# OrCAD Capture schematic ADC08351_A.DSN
size B; title: SCHEMATIC; rev: A; note: ADC08351EVM
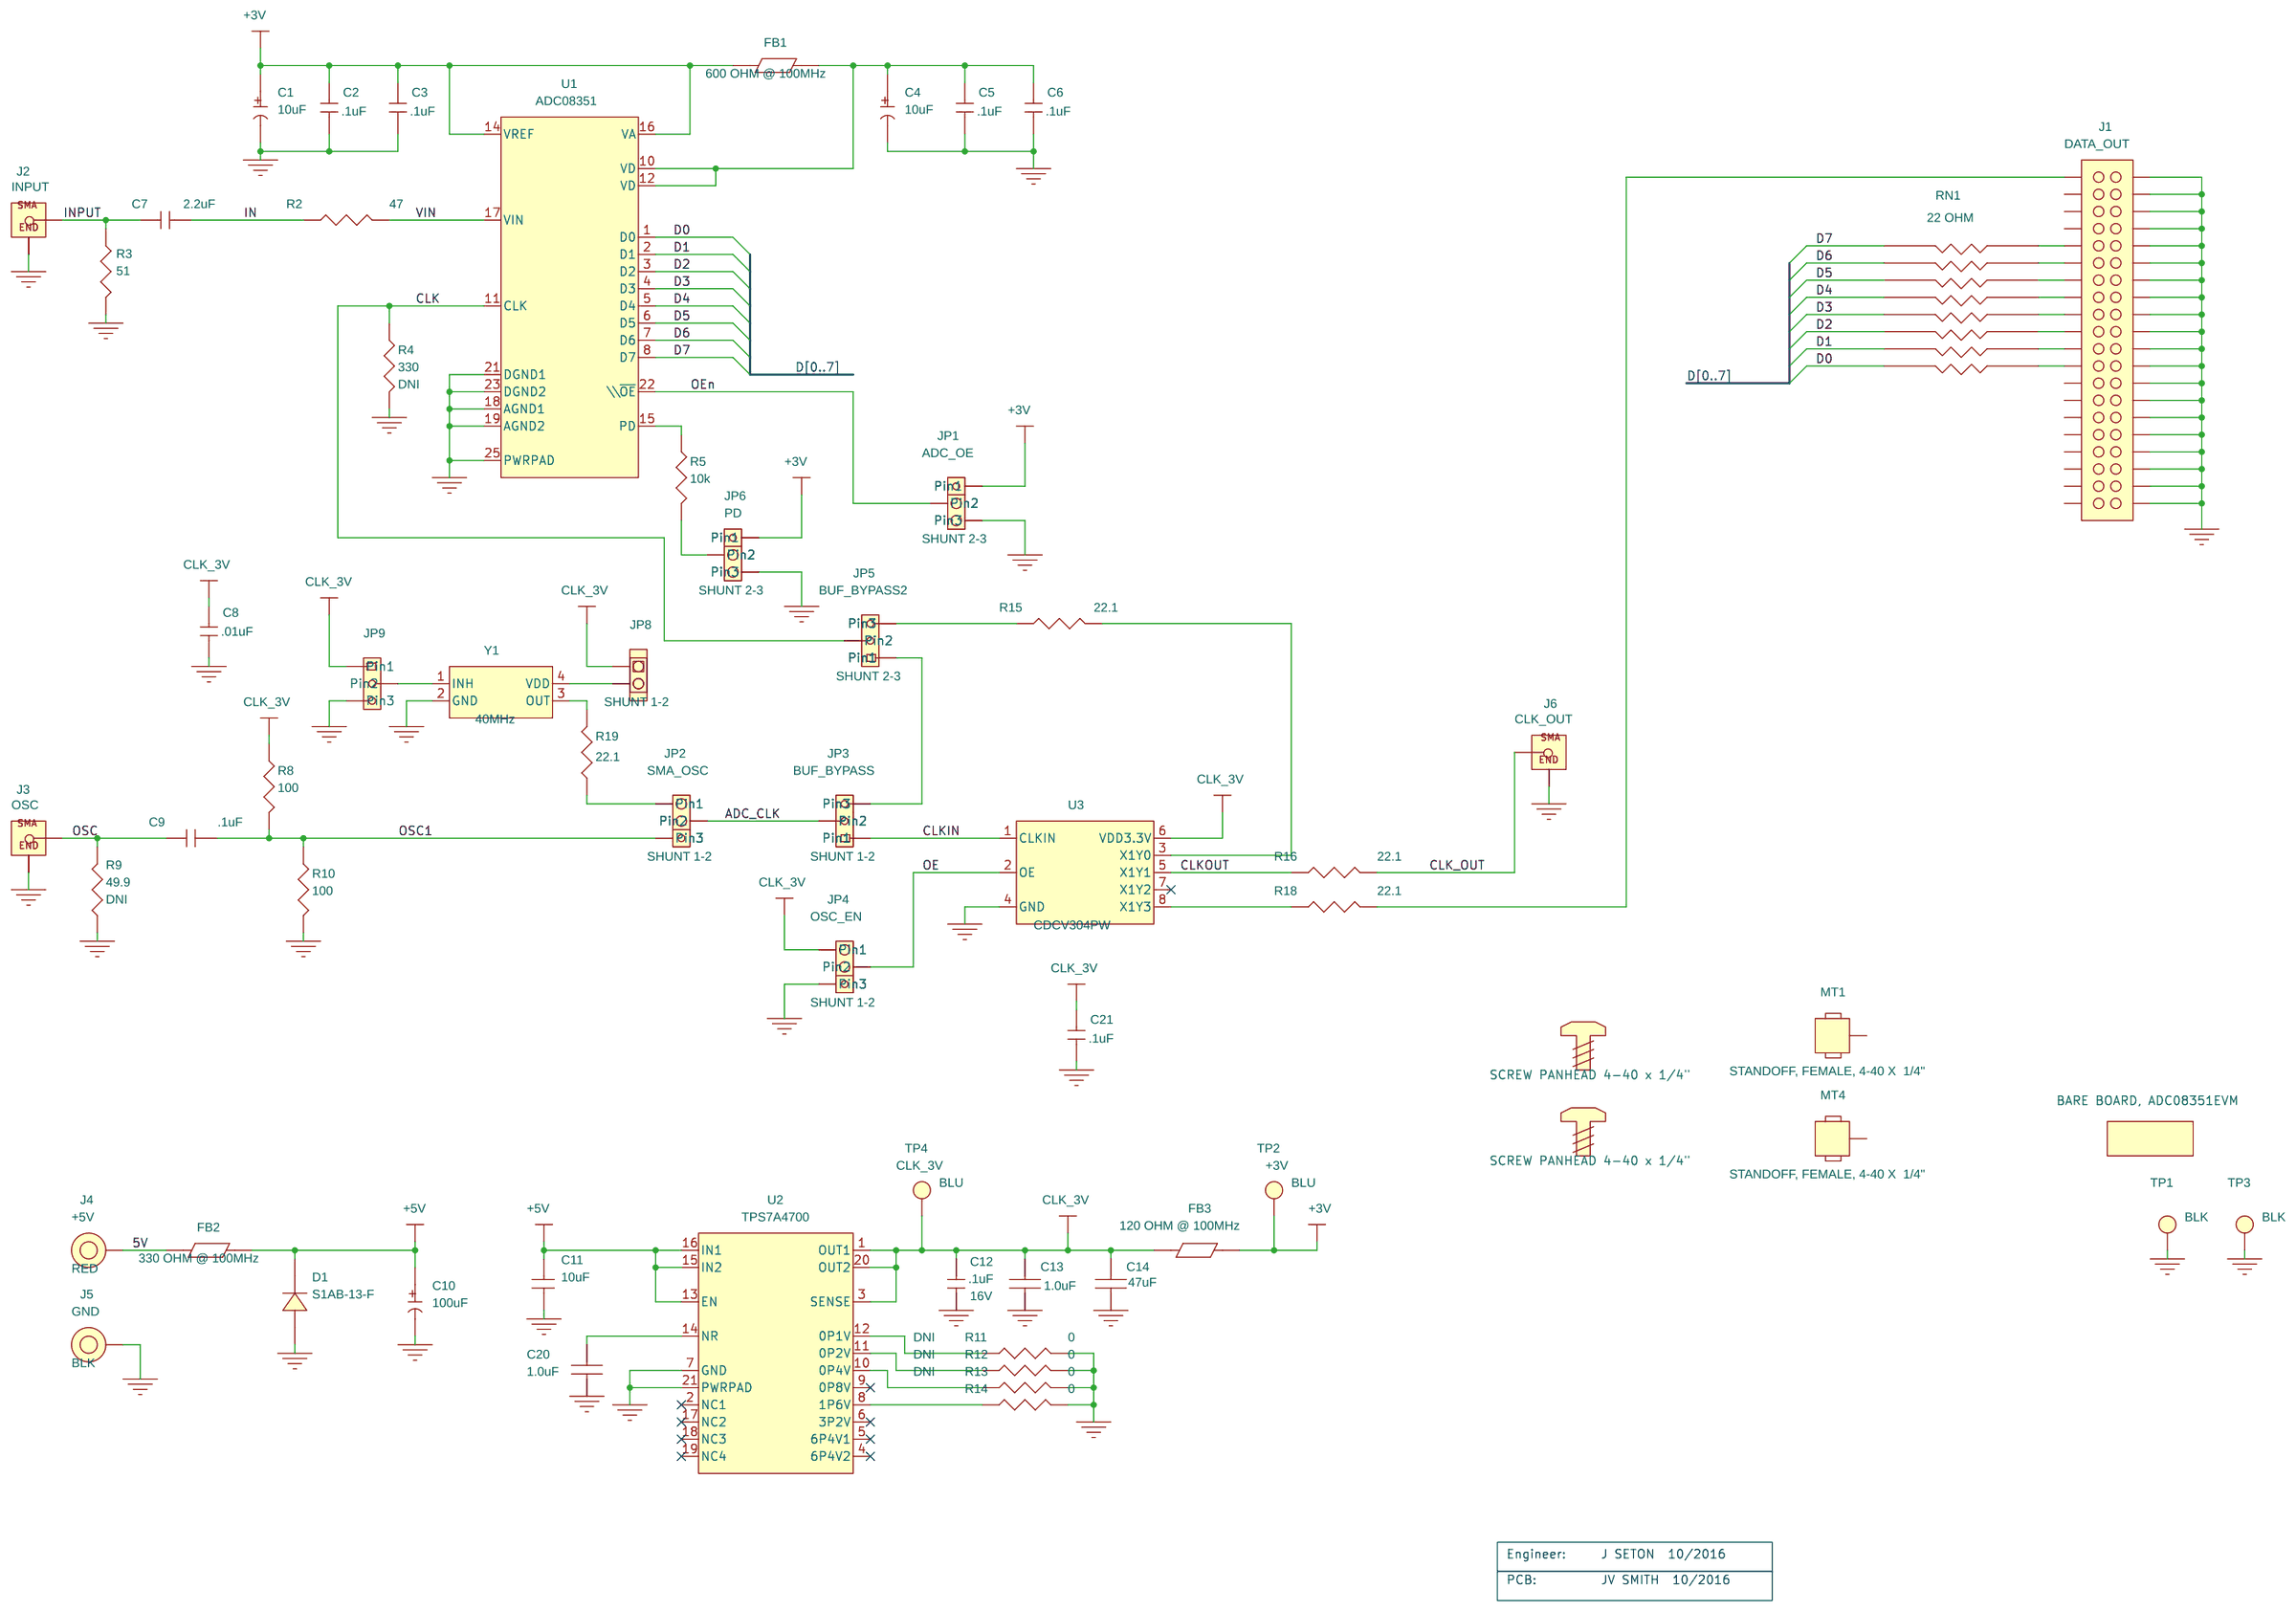
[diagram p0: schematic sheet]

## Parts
C1  10uF  [TANT_A]
C2  .1uF  [0402]
C3  .1uF  [0402]
C4  10uF  [TANT_A]
C5  .1uF  [0402]
C6  .1uF  [0402]
C7  2.2uF  [0402]
C8  .01uF  [0402]
C9  .1uF  [0402]
C10  100uF  [TANT_D]
C11  10uF  [0805]
C12  .1uF  [0402]
C13  1.0uF  [0603]
C14  47uF  [1206]
C20  1.0uF  [0603]
C21  .1uF  [0402]
D1  S1AB-13-F  [DIODE_S1AB_SMB]
FB1  600 OHM @ 100MHz  [IND_0603]
FB2  330 OHM @ 100MHz  [IND_0603]
FB3  120 OHM @ 100MHz  [1206]
J1  HDR, THVT, 40POS, .100  [HDR_THVT_2x20_100_M]
J2  SMA, THVT,  50OHMS  [SMA_THVT_312X312]
J3  SMA, THVT,  50OHMS  [SMA_THVT_312X312]
J4  RED  [JACK_THVT_BANANA_315DRILL]
J5  BLK  [JACK_THVT_BANANA_315DRILL]
J6  SMA, THVT,  50OHMS  [SMA_THVT_312X312]
JP1  HEADER, 3POS, .100  [HDR_THVT_1x3_100_M]
JP2  HEADER, 3POS, .100  [HDR_THVT_1x3_100_M]
JP3  HEADER, 3POS, .100  [HDR_THVT_1x3_100_M]
JP4  HEADER, 3POS, .100  [HDR_THVT_1x3_100_M]
JP5  HEADER, 3POS, .100  [HDR_THVT_1x3_100_M]
JP6  HEADER, 3POS, .100  [HDR_THVT_1x3_100_M]
JP8  HDR, 2POS, .100  [HDR_THVT_1X2_100_M]
JP9  HEADER, 3POS, .100  [HDR_THVT_1x3_100_M]
MT1  STANDOFF, FEMALE, 4-40 X  1/4"  [MFG125_PLATED]
MT4  STANDOFF, FEMALE, 4-40 X  1/4"  [MFG125_PLATED]
R2  47  [0402]
R3  51  [0402]
R4  330  [0402]
R5  10k  [0402]
R8  100  [0402]
R9  49.9  [0402]
R10  100  [0402]
R11  0  [0402]
R12  0  [0402]
R13  0  [0402]
R14  0  [0402]
R15  22.1  [0402]
R16  22.1  [0402]
R18  22.1  [0402]
R19  22.1  [0402]
RN1  22 OHM  [RNET_16_225x445_50]
TP1  BLK  [TP_THVT_100_RND_GND]
TP2  BLU  [TP_THVT_100_RND]
TP3  BLK  [TP_THVT_100_RND_GND]
TP4  BLU  [TP_THVT_100_RND]
U1  ADC08351  [WQFN_24_157x197_0p50MM]
U2  TPS7A4700  [qfn20_rgw_p65pitch]
U3  CDCV304PW  [TSSOP_8_177x122_26]
Y1  40MHz  [XTAL_4_SM_102x130]
Z_BOARD2  BARE BOARD, ADC08351EVM
Z_SCREW1  SCREW PANHEAD 4-40 x 1/4"
Z_SCREW2  SCREW PANHEAD 4-40 x 1/4"
Z_SH-H1  SHUNT-HEADER
Z_SH-H2  SHUNT-HEADER
Z_SH-H3  SHUNT-HEADER
Z_SH-H4  SHUNT-HEADER
Z_SH-H5  SHUNT-HEADER
Z_SH-H6  SHUNT-HEADER
Z_SH-J1  SHUNT- HEADER

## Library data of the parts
C1 C4 = CAP_TANT_A_0
C2 C3 C5 C6 C9 C21 = CAP_0402_0.1uF
C7 = CAP_0402_2.2uF
C8 = CAP_0402_0.01uF
C10 = CAP_TANT_D_0: Mfr_Part_Number: T521D107M020ATE055
C11 = CAP_NP_1: Mfr_Name: MURATA; Mfr_Part_Number: GRM21BR61E106KA73L; TOL: 10%; VOLTAGE: 25V
C12 = CAP0603: Mfr_Name: MURATA; Mfr_Part_Number: GRM155R71C104KA88D; TOL: 10%; Voltage: 16V
C13 C20 = CAP_NP_0: Mfr_Name: TDK CORP; Mfr_Part_Number: C1608X7R1C105K080AC; TOL: 10%; VOLTAGE: 16V
C14 = CAP_NP_0: Mfr_Name: MURATA; Mfr_Part_Number: GRM31CR61A476ME15L; TOL: 20%; VOLTAGE: 10V
D1 = DIODE_S1BB
FB1 = FERRITE_BEAD_0603_600_H: Mfr_Part_Number: BLM18AG601SN1D
FB2 = FERRITE_BEAD_0603_600_H: Mfr_Part_Number: BLM18PG331SN1D
FB3 = FERRITE_BEAD_1206_120_H: Mfr_Part_Number: BLM31PG121SN1L
J1 = HEADER_2x20_100: Mfr_Part_Number: TSW-120-07-G-D; TI_SILKTEXT: DATA_OUT
J2 = TMP_102603: Mfr_Part_Number: 142-0701-201; TI_Silktext: INPUT
J3 = TMP_102603: Mfr_Part_Number: 142-0701-201; TI_Silktext: OSC
J4 = BANANA_JACK_RED_RoHS: Mfr_Name: ALLIED ELECTRONICS; Mfr_Part_Number: ST-351A; TI_Silktext: +5V
J5 = BANANA_JACK_BLK_RoHS: Mfr_Name: ALLIED ELECTRONICS; Mfr_Part_Number: ST-351B; TI_Silktext: GND
J6 = TMP_102603: Mfr_Part_Number: 142-0701-201; TI_Silktext: CLK_OUT
JP1 = JUMPER_1X3_100: Note: SHUNT 2-3; TI_Silktext: ADC_OE
JP2 = JUMPER_1X3_100: Note: SHUNT 1-2; TI_Silktext: SMA_OSC
JP3 = JUMPER_1X3_100: Note: SHUNT 1-2; TI_Silktext: BUF_BYPASS
JP4 = JUMPER_1X3_100: Note: SHUNT 1-2; TI_Silktext: OSC_EN
JP5 = JUMPER_1X3_100: Note: SHUNT 2-3; TI_Silktext: BUF_BYPASS2
JP6 = JUMPER_1X3_100: Note: SHUNT 2-3; TI_Silktext: PD
JP8 = JUMPER_1X2_100: Note: SHUNT 1-2; SILK: SILK
JP9 = JUMPER_1X3_100
MT1 MT4 = MOUNTING_HOLE_1_3_16: Mfr_Name: KEYSTONE; Mfr_Part_Number: 1891
R2 = Res_0402_47
R3 = Res_0402_51_.5%: Mfr_Part_Number: ERA-2AED510X; TOL: .1%
R4 = Res_0402_330: Mfr_Part_Number: ERJ-2RKF3300X_DNI; Note: DNI
R5 = Res_0402_10k
R8 R10 = Res_0402_100
R9 = Res_0402_49.9_H: Mfr_Part_Number: ERJ-2RKF49R9X_DNI; Note: DNI
R11-R13 = R: Mfr_Name: PANASONIC; Mfr_Part_Number: ERJ-2GE0R00X_DNI; Note: DNI; TOL: 5%
R14 = R: Mfr_Name: PANASONIC; Mfr_Part_Number: ERJ-2GE0R00X; TOL: 5%
R15 R16 R18 R19 = Res_0402_22.1_H
RN1 = RESNW_IS_8: Mfr_Name: BOURNS; Mfr_Part_Number: 4816P-1-220LF
TP1 TP3 = TESTPOINT_BLK
TP2 = TESTPOINT_BLUE: TI_SILKTEXT: +3V
TP4 = TESTPOINT_BLUE: TI_SILKTEXT: CLK_3V
U1 = ADC08351
U2 = TPS7A4700: Mfr_Name: Texas Instruments; Mfr_Part_Number: TPS7A4700RGWT
U3 = CDCV304PW
Y1 = OSC_4_SM_KYOCERA_40MHz: Mfr_Part_Number: KC3225A40.0000C3GE00
Z_BOARD2 = BARE_BOARD: Mfr_Name: TTM; Mfr_Part_Number: ADC08351 REV A
Z_SCREW1 Z_SCREW2 = STANDOFF-SCREW_3_4: Mfr_Part_Number: PMSSS 440 0025 PH
Z_SH-H1-Z_SH-H6 = SHUNT-HEADER_-_3POS
Z_SH-J1 = SHUNT-HEADER_-_2POS

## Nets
5V: FB2.1 J4.1
+3V: C1.1 C2.1 C3.1 FB1.1 FB3.2 JP1.1(Pin1) JP6.1(Pin1) TP2.1(TP) U1.14(VREF) U1.16(VA)
+5V: C10.1 C11.1 D1.2(CATHODE) FB2.2 U2.13(EN) U2.15(IN2) U2.16(IN1)
GND: C1.2 C2.2 C3.2 C4.2 C5.2 C6.2 C8.2 C10.2 C11.2 C12.2 C13.2 C14.2 C20.2 C21.2 D1.1(ANODE) J1.2 J1.4 J1.6 J1.8 J1.10 J1.12 J1.14 J1.16 J1.18 J1.20 J1.22 J1.24 J1.26 J1.28 J1.30 J1.32 J1.34 J1.36 J1.38 J1.40 J2.2(GND) J2.3(GND) J2.4(GND) J2.5(GND) J3.2(GND) J3.3(GND) J3.4(GND) J3.5(GND) J5.1 J6.2(GND) J6.3(GND) J6.4(GND) J6.5(GND) JP1.3(Pin3) JP4.3(Pin3) JP6.3(Pin3) JP9.3(Pin3) R3.2 R4.2 R9.1 R10.2 R11.1 R12.1 R13.1 R14.1 TP1.1(TP) TP3.1(TP) U1.18(AGND1) U1.19(AGND2) U1.21(DGND1) U1.23(DGND2) U1.25(PWRPAD) U2.7(GND) U2.21(PWRPAD) U3.4(GND) Y1.2(GND)
VIN: R2.2 U1.17(VIN)
ADC_CLK: JP2.2(Pin2) JP3.2(Pin2)
CLK: JP5.2(Pin2) R4.1 U1.11(CLK)
CLK_3V: C8.1 C12.1 C13.1 C14.1 C21.1 FB3.1 JP4.1(Pin1) JP8.1 JP9.1(Pin1) R8.1 TP4.1(TP) U2.1(OUT1) U2.3(SENSE) U2.20(OUT2) U3.6(VDD3.3V)
CLK_OUT: J6.1(CENTER) R16.2
CLKIN: JP3.1(Pin1) U3.1(CLKIN)
CLKOUT: R16.1 U3.5(X1Y1)
D0: RN1.16 U1.1(D0)
D1: RN1.15 U1.2(D1)
D2: RN1.14 U1.3(D2)
D3: RN1.13 U1.4(D3)
D4: RN1.12 U1.5(D4)
D5: RN1.11 U1.6(D5)
D6: RN1.10 U1.7(D6)
D7: RN1.9 U1.8(D7)
IN: C7.2 R2.1
INPUT: C7.1 J2.1(CENTER) R3.1
OE: JP4.2(Pin2) U3.2(OE)
OEn: JP1.2(Pin2) U1.22(\\~{OE})
OSC: C9.1 J3.1(CENTER) R9.2
OSC1: C9.2 JP2.3(Pin3) R8.2 R10.1
N19763021: C4.1 C5.1 C6.1 FB1.2 U1.10(VD) U1.12(VD)
N19764908: R5.1 U1.15(PD)
N19769118: R19.2 Y1.3(OUT)
N19769226: JP2.1(Pin1) R19.1
N19785120: C20.1 U2.14(NR)
N19785142: R14.2 U2.8(1P6V)
N19785144: R12.2 U2.11(0P2V)
N19785146: R11.2 U2.12(0P1V)
N19785156: R13.2 U2.10(0P4V)
N19799665: R15.2 U3.3(X1Y0)
N19799687: R18.1 U3.8(X1Y3)
N19799717: J1.1 R18.2
N19818955: J1.23 RN1.1
N19818957: J1.21 RN1.2
N19818959: J1.19 RN1.3
N19818961: J1.17 RN1.4
N19819026: J1.9 RN1.8
N19819028: J1.11 RN1.7
N19819030: J1.13 RN1.6
N19819032: J1.15 RN1.5
N19819185: JP3.3(Pin3) JP5.1(Pin1)
N19819218: JP5.3(Pin3) R15.1
N19819979: JP6.2(Pin2) R5.2
N19821064: JP9.2(Pin2) Y1.1(INH)
N19821339: JP8.2 Y1.4(VDD)

Not connected (* = marked no-connect by the designer): J1 3 5 7 25 27 29 31 33 35 37 39; MT1 1; MT4 1; U2 2(NC1)* 4(6P4V2)* 5(6P4V1)* 6(3P2V)* 9(0P8V)* 17(NC2)* 18(NC3)* 19(NC4)*; U3 7(X1Y2)*

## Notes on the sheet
- Engineer:
- J SETON  10/2016
- PCB:
- JV SMITH  10/2016
